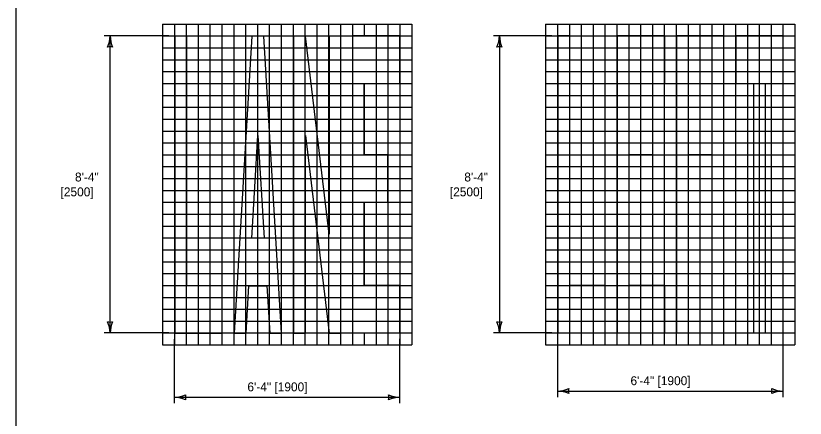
# Model space of a CAD drawing. Extents: x 49991.4 to 50021, y 49987.6 to 50011.4.
# Drawn here: x 50000.34 to 50005.66, y 50005.84 to 50008.55 of the extents above; entities that cross this region are included whole.
import ezdxf

# ---------------------------------------------------------------- set-up
doc = ezdxf.new("R2010")
doc.units = 0
for name, color, linetype in [('Level 1', 7, 'Continuous'), ('Level 2', 7, 'Continuous'), ('Level 3', 7, 'Continuous'), ('Level 9', 7, 'Continuous')]:
    doc.layers.add(name, color=color, linetype=linetype)

msp = doc.modelspace()

# ---------------------------------------------------------------- linework, layer by layer
at = {"layer": 'Level 1'}
for p, q in [((50001.4074, 50008.4148), (50001.4074, 50006.4142)), ((50001.4874, 50008.4148), (50001.4074, 50008.4148)), ((50001.4874, 50007.2145), (50001.4874, 50008.4148)), ((50001.9273, 50008.4148), (50001.8074, 50006.4142)), ((50002.0073, 50008.4148), (50001.9273, 50008.4148)), ((50002.1273, 50006.4142), (50002.0073, 50008.4148)), ((50002.2889, 50008.4148), (50002.2072, 50008.4148)), ((50002.2072, 50008.4148), (50002.2072, 50006.4142)), ((50002.4472, 50007.0825), (50002.2889, 50008.4148)), ((50002.5272, 50008.4148), (50002.4472, 50008.4148)), ((50002.4472, 50008.4148), (50002.4472, 50007.0825)), ((50002.5272, 50006.4142), (50002.5272, 50008.4148)), ((50002.924, 50008.4165), (50002.604, 50008.4165)), ((50002.604, 50008.4165), (50002.604, 50006.4159)), ((50002.924, 50008.0965), (50002.924, 50008.4165)), ((50003.9891, 50008.4169), (50003.9891, 50006.4163)), ((50004.0691, 50008.4169), (50003.9891, 50008.4169)), ((50003.9891, 50008.4169), (50003.9891, 50006.4163)), ((50004.0691, 50008.4169), (50003.9891, 50008.4169)), ((50004.0691, 50007.2164), (50004.0691, 50008.4169)), ((50004.0691, 50007.2164), (50004.0691, 50008.4169)), ((50004.7096, 50008.417), (50004.3897, 50008.417)), ((50004.3897, 50008.417), (50004.3897, 50006.4164)), ((50004.7096, 50008.417), (50004.3897, 50008.417)), ((50004.3897, 50008.417), (50004.3897, 50006.4164)), ((50004.7096, 50008.0969), (50004.7096, 50008.417)), ((50004.7096, 50008.0969), (50004.7096, 50008.417)), ((50005.1088, 50008.4169), (50004.7889, 50008.4169)), ((50004.7889, 50008.4169), (50004.7889, 50006.4163)), ((50005.1088, 50008.4169), (50004.7889, 50008.4169)), ((50004.7889, 50008.4169), (50004.7889, 50006.4163)), ((50005.1088, 50008.0967), (50005.1088, 50008.4169)), ((50005.1088, 50008.0967), (50005.1088, 50008.4169)), ((50005.5088, 50008.4169), (50005.1888, 50008.4169)), ((50005.1888, 50008.4169), (50005.1888, 50008.0967)), ((50005.5088, 50008.4169), (50005.1888, 50008.4169)), ((50005.1888, 50008.4169), (50005.1888, 50008.0967)), ((50005.5088, 50008.0967), (50005.5088, 50008.4169)), ((50005.5088, 50008.0967), (50005.5088, 50008.4169)), ((50002.6841, 50007.6162), (50002.6841, 50008.0965)), ((50002.6841, 50008.0965), (50002.924, 50008.0965)), ((50004.4696, 50007.6168), (50004.4696, 50008.0969)), ((50004.4696, 50008.0969), (50004.7096, 50008.0969)), ((50004.4696, 50007.6168), (50004.4696, 50008.0969)), ((50004.4696, 50008.0969), (50004.7096, 50008.0969)), ((50004.8689, 50007.6166), (50004.8689, 50008.0967)), ((50004.8689, 50008.0967), (50005.1088, 50008.0967)), ((50004.8689, 50007.6166), (50004.8689, 50008.0967)), ((50004.8689, 50008.0967), (50005.1088, 50008.0967)), ((50005.1888, 50008.0967), (50005.3088, 50008.0967)), ((50005.1888, 50008.0967), (50005.3088, 50008.0967)), ((50005.3088, 50008.0967), (50005.3088, 50006.4163)), ((50005.3088, 50008.0967), (50005.3088, 50006.4163)), ((50005.3888, 50006.4163), (50005.3888, 50008.0967)), ((50005.3888, 50008.0967), (50005.5088, 50008.0967)), ((50005.3888, 50006.4163), (50005.3888, 50008.0967)), ((50005.3888, 50008.0967), (50005.5088, 50008.0967)), ((50001.9265, 50007.0544), (50001.9681, 50007.7459)), ((50001.9681, 50007.7459), (50002.0089, 50007.0544)), ((50002.2872, 50006.4142), (50002.2872, 50007.7466)), ((50002.2872, 50007.7466), (50002.4472, 50006.4142)), ((50002.844, 50007.6162), (50002.6841, 50007.6162)), ((50002.844, 50007.2962), (50002.844, 50007.6162)), ((50004.6296, 50007.6168), (50004.4696, 50007.6168)), ((50004.6296, 50007.6168), (50004.4696, 50007.6168)), ((50004.6296, 50007.2967), (50004.6296, 50007.6168)), ((50004.6296, 50007.2967), (50004.6296, 50007.6168)), ((50005.0288, 50007.6166), (50004.8689, 50007.6166)), ((50005.0288, 50007.6166), (50004.8689, 50007.6166)), ((50005.0288, 50007.2966), (50005.0288, 50007.6166)), ((50005.0288, 50007.2966), (50005.0288, 50007.6166)), ((50002.6841, 50006.7359), (50002.6841, 50007.2962)), ((50002.6841, 50007.2962), (50002.844, 50007.2962)), ((50004.4696, 50006.7365), (50004.4696, 50007.2967)), ((50004.4696, 50007.2967), (50004.6296, 50007.2967)), ((50004.4696, 50006.7365), (50004.4696, 50007.2967)), ((50004.4696, 50007.2967), (50004.6296, 50007.2967)), ((50004.8689, 50006.4163), (50004.8689, 50007.2966)), ((50004.8689, 50007.2966), (50005.0288, 50007.2966)), ((50004.8689, 50006.4163), (50004.8689, 50007.2966)), ((50004.8689, 50007.2966), (50005.0288, 50007.2966)), ((50001.4874, 50006.7342), (50001.4874, 50007.2145)), ((50004.0691, 50006.7363), (50004.0691, 50007.2164)), ((50004.0691, 50006.7363), (50004.0691, 50007.2164)), ((50002.0089, 50007.0544), (50001.9265, 50007.0544)), ((50001.7274, 50006.7342), (50001.4874, 50006.7342)), ((50001.7274, 50006.4142), (50001.7274, 50006.7342)), ((50001.8873, 50006.4142), (50001.9065, 50006.7342)), ((50001.9065, 50006.7342), (50002.0281, 50006.7342)), ((50002.0281, 50006.7342), (50002.0473, 50006.4142)), ((50002.924, 50006.7359), (50002.6841, 50006.7359)), ((50002.924, 50006.4159), (50002.924, 50006.7359)), ((50004.3091, 50006.7363), (50004.0691, 50006.7363)), ((50004.3091, 50006.7363), (50004.0691, 50006.7363)), ((50004.3091, 50006.4163), (50004.3091, 50006.7363)), ((50004.3091, 50006.4163), (50004.3091, 50006.7363)), ((50004.7096, 50006.7365), (50004.4696, 50006.7365)), ((50004.7096, 50006.7365), (50004.4696, 50006.7365)), ((50004.7096, 50006.4164), (50004.7096, 50006.7365)), ((50004.7096, 50006.4164), (50004.7096, 50006.7365)), ((50001.4074, 50006.4142), (50001.7274, 50006.4142)), ((50001.8074, 50006.4142), (50001.8074, 50006.4142)), ((50001.8074, 50006.4142), (50001.8873, 50006.4142)), ((50002.0473, 50006.4142), (50002.1273, 50006.4142)), ((50002.2072, 50006.4142), (50002.2872, 50006.4142)), ((50002.4472, 50006.4142), (50002.5272, 50006.4142)), ((50002.604, 50006.4159), (50002.924, 50006.4159)), ((50003.9891, 50006.4163), (50004.3091, 50006.4163)), ((50003.9891, 50006.4163), (50004.3091, 50006.4163)), ((50004.3897, 50006.4164), (50004.7096, 50006.4164)), ((50004.3897, 50006.4164), (50004.7096, 50006.4164)), ((50004.7889, 50006.4163), (50004.8689, 50006.4163)), ((50004.7889, 50006.4163), (50004.8689, 50006.4163)), ((50005.3088, 50006.4163), (50005.3888, 50006.4163)), ((50005.3088, 50006.4163), (50005.3888, 50006.4163))]:
    msp.add_line(p, q, dxfattribs=at)
msp.add_lwpolyline([(50008.6146, 50011.2628), (50000.3356, 50011.2628), (50000.3356, 50000.0624), (50008.6146, 50000.0624)], close=True, dxfattribs=at)
at = {"layer": 'Level 3'}
for p, q in [((50001.3674, 50008.4165), (50000.9316, 50008.4165)), ((50000.9716, 50006.4159), (50000.9716, 50008.4165)), ((50003.9491, 50008.4165), (50003.5556, 50008.4165)), ((50003.5956, 50008.4165), (50003.5956, 50006.4159)), ((50005.5065, 50008.0567), (50005.5065, 50005.9843)), ((50001.3674, 50006.4159), (50000.9316, 50006.4159)), ((50003.9491, 50006.4159), (50003.5556, 50006.4159)), ((50001.4044, 50005.9428), (50001.4044, 50006.3742)), ((50002.9241, 50005.9428), (50002.9241, 50006.3759)), ((50003.9869, 50006.3763), (50003.9869, 50005.9843)), ((50001.4044, 50005.9828), (50002.9241, 50005.9828)), ((50003.9869, 50006.0243), (50005.5065, 50006.0243))]:
    msp.add_line(p, q, dxfattribs=at)
for centre, radius, start, end in [((50000.7495, 50008.4257), 0.2223, 337.456, 357.6395), ((50001.2043, 50008.428), 0.233, 182.8273, 202.0772), ((50003.3734, 50008.4257), 0.2223, 337.456, 357.6395), ((50003.8283, 50008.428), 0.233, 182.8273, 202.0772), ((50000.9716, 50008.2883), 0.0548, 72.1388, 107.8612), ((50003.5956, 50008.2883), 0.0548, 72.1388, 107.8612), ((50000.9716, 50006.5441), 0.0548, 252.1388, 287.8612), ((50000.7389, 50006.4044), 0.233, 2.8273, 22.0772), ((50001.1938, 50006.4067), 0.2223, 157.456, 177.6395), ((50003.5956, 50006.5441), 0.0548, 252.1388, 287.8612), ((50003.3629, 50006.4044), 0.233, 2.8273, 22.0772), ((50003.8177, 50006.4067), 0.2223, 157.456, 177.6395), ((50003.9777, 50006.2465), 0.2223, 272.3605, 292.544), ((50004.1151, 50006.0243), 0.0548, 162.1388, 197.8612), ((50005.5157, 50006.2465), 0.2223, 247.456, 267.6395), ((50005.3783, 50006.0243), 0.0548, 342.1388, 17.8612), ((50001.3953, 50006.2049), 0.2223, 272.3605, 292.544), ((50001.393, 50005.7501), 0.233, 67.9228, 87.1727), ((50001.5327, 50005.9828), 0.0548, 162.1388, 197.8612), ((50002.9333, 50006.2049), 0.2223, 247.456, 267.6395), ((50002.7959, 50005.9828), 0.0548, 342.1388, 17.8612), ((50002.9356, 50005.7501), 0.233, 92.8273, 112.0772), ((50003.9754, 50005.7916), 0.233, 67.9228, 87.1727), ((50005.518, 50005.7916), 0.233, 92.8273, 112.0772)]:
    msp.add_arc(centre, radius, start, end, dxfattribs=at)
at = {"layer": 'Level 9'}
for p, q in [((50001.3245, 50008.4966), (50001.3245, 50006.3358)), ((50001.3245, 50008.4966), (50003.0041, 50008.4966)), ((50001.4044, 50008.4966), (50001.4044, 50006.3358)), ((50001.4844, 50008.4966), (50001.4844, 50006.3358)), ((50001.5644, 50008.4966), (50001.5644, 50006.3358)), ((50001.6444, 50008.4966), (50001.6444, 50006.3358)), ((50001.7244, 50008.4966), (50001.7244, 50006.3358)), ((50001.8044, 50008.4966), (50001.8044, 50006.3358)), ((50001.8843, 50008.4966), (50001.8843, 50006.3358)), ((50001.9643, 50008.4966), (50001.9643, 50006.3358)), ((50002.0443, 50008.4966), (50002.0443, 50006.3358)), ((50002.1243, 50008.4966), (50002.1243, 50006.3358)), ((50002.2043, 50008.4966), (50002.2043, 50006.3358)), ((50002.2843, 50008.4966), (50002.2843, 50006.3358)), ((50002.3642, 50008.4966), (50002.3642, 50006.3358)), ((50002.4442, 50008.4966), (50002.4442, 50006.3358)), ((50002.5242, 50008.4966), (50002.5242, 50006.3358)), ((50002.6042, 50008.4966), (50002.6042, 50006.3358)), ((50002.6842, 50008.4966), (50002.6842, 50008.4165)), ((50002.7642, 50008.4966), (50002.7642, 50006.3358)), ((50002.8441, 50008.4966), (50002.8441, 50006.3358)), ((50002.9241, 50008.4966), (50002.9241, 50006.3358)), ((50003.0041, 50008.4966), (50003.0041, 50006.3358)), ((50003.9069, 50008.4966), (50005.5865, 50008.4966)), ((50003.9069, 50008.4966), (50003.9069, 50006.3358)), ((50003.9869, 50008.4966), (50003.9869, 50006.3358)), ((50004.0669, 50008.4966), (50004.0669, 50006.3358)), ((50004.1468, 50008.4966), (50004.1468, 50006.3358)), ((50004.2268, 50008.4966), (50004.2268, 50006.3358)), ((50004.3068, 50008.4966), (50004.3068, 50006.3358)), ((50004.3868, 50008.4966), (50004.3868, 50006.3358)), ((50004.4668, 50008.4966), (50004.4668, 50006.3358)), ((50004.5468, 50008.4966), (50004.5468, 50006.3358)), ((50004.6267, 50008.4966), (50004.6267, 50006.3358)), ((50004.7067, 50008.4966), (50004.7067, 50006.3358)), ((50004.7867, 50008.4966), (50004.7867, 50006.3358)), ((50004.8667, 50008.4966), (50004.8667, 50006.3358)), ((50004.9467, 50008.4966), (50004.9467, 50006.3358)), ((50005.0267, 50008.4966), (50005.0267, 50006.3358)), ((50005.1066, 50008.4966), (50005.1066, 50006.3358)), ((50005.1866, 50008.4966), (50005.1866, 50006.3358)), ((50005.2666, 50008.4966), (50005.2666, 50006.3358)), ((50005.3466, 50008.4966), (50005.3466, 50006.3358)), ((50005.4266, 50008.4966), (50005.4266, 50006.3358)), ((50005.5065, 50008.4966), (50005.5065, 50006.3358)), ((50005.5865, 50008.4966), (50005.5865, 50006.3358)), ((50001.3245, 50008.4165), (50003.0041, 50008.4165)), ((50003.9069, 50008.4165), (50005.5865, 50008.4165)), ((50001.3245, 50008.3365), (50003.0041, 50008.3365)), ((50003.9069, 50008.3365), (50005.5865, 50008.3365)), ((50001.3245, 50008.2565), (50003.0041, 50008.2565)), ((50003.9069, 50008.2565), (50005.5865, 50008.2565)), ((50001.3245, 50008.1765), (50003.0041, 50008.1765)), ((50001.4044, 50008.1765), (50002.9241, 50008.1765)), ((50003.9069, 50008.1765), (50005.5865, 50008.1765)), ((50003.9869, 50008.1765), (50005.5065, 50008.1765)), ((50004.706, 50008.1765), (50004.706, 50008.1765)), ((50001.3245, 50008.0964), (50003.0041, 50008.0964)), ((50001.4044, 50008.0964), (50002.9241, 50008.0964)), ((50002.6842, 50008.0965), (50002.6842, 50007.6163)), ((50003.9069, 50008.0964), (50005.5865, 50008.0964)), ((50003.9869, 50008.0964), (50005.5065, 50008.0964)), ((50001.3245, 50008.0164), (50003.0041, 50008.0164)), ((50003.9069, 50008.0164), (50005.5865, 50008.0164)), ((50001.3245, 50007.9364), (50003.0041, 50007.9364)), ((50003.9069, 50007.9364), (50005.5865, 50007.9364)), ((50001.3245, 50007.8563), (50003.0041, 50007.8563)), ((50003.9069, 50007.8563), (50005.5865, 50007.8563)), ((50001.3245, 50007.7763), (50003.0041, 50007.7763)), ((50003.9069, 50007.7763), (50005.5865, 50007.7763)), ((50001.3245, 50007.6963), (50003.0041, 50007.6963)), ((50003.9069, 50007.6963), (50005.5865, 50007.6963)), ((50001.3245, 50007.6163), (50003.0041, 50007.6163)), ((50003.9069, 50007.6163), (50005.5865, 50007.6163)), ((50001.3245, 50007.5362), (50003.0041, 50007.5362)), ((50003.9069, 50007.5362), (50005.5865, 50007.5362)), ((50001.3245, 50007.4562), (50003.0041, 50007.4562)), ((50003.9069, 50007.4562), (50005.5865, 50007.4562)), ((50001.3245, 50007.3762), (50003.0041, 50007.3762)), ((50003.9069, 50007.3762), (50005.5865, 50007.3762)), ((50001.3245, 50007.2962), (50003.0041, 50007.2962)), ((50002.6842, 50007.2961), (50002.6842, 50006.736)), ((50003.9069, 50007.2962), (50005.5865, 50007.2962)), ((50001.3245, 50007.2161), (50003.0041, 50007.2161)), ((50003.9069, 50007.2161), (50005.5865, 50007.2161)), ((50001.3245, 50007.1361), (50003.0041, 50007.1361)), ((50003.9069, 50007.1361), (50005.5865, 50007.1361)), ((50001.3245, 50007.0561), (50003.0041, 50007.0561)), ((50003.9069, 50007.0561), (50005.5865, 50007.0561)), ((50001.3245, 50006.976), (50003.0041, 50006.976)), ((50003.9069, 50006.976), (50005.5865, 50006.976)), ((50001.3245, 50006.896), (50003.0041, 50006.896)), ((50003.9069, 50006.896), (50005.5865, 50006.896)), ((50001.3245, 50006.816), (50003.0041, 50006.816)), ((50003.9069, 50006.816), (50005.5865, 50006.816)), ((50001.3245, 50006.736), (50003.0041, 50006.736)), ((50003.9069, 50006.736), (50005.5865, 50006.736)), ((50001.3245, 50006.6559), (50003.0041, 50006.6559)), ((50003.9069, 50006.6559), (50005.5865, 50006.6559)), ((50001.3245, 50006.5759), (50003.0041, 50006.5759)), ((50003.9069, 50006.5759), (50005.5865, 50006.5759)), ((50001.3245, 50006.4959), (50003.0041, 50006.4959)), ((50003.9069, 50006.4959), (50005.5865, 50006.4959)), ((50001.3245, 50006.4159), (50003.0041, 50006.4159)), ((50002.6842, 50006.4158), (50002.6842, 50006.3358)), ((50003.9069, 50006.4159), (50005.5865, 50006.4159)), ((50001.3245, 50006.3358), (50003.0041, 50006.3358)), ((50003.9069, 50006.3358), (50005.5865, 50006.3358))]:
    msp.add_line(p, q, dxfattribs=at)

# ---------------------------------------------------------------- texts
at = {"layer": 'Level 2'}
for s, p in [('8\'-4"', (50000.7347, 50007.4363)), ('8\'-4"', (50003.3586, 50007.4363)), ('[2500]', (50000.6373, 50007.3363)), ('[2500]', (50003.2613, 50007.3363)), ('6\'-4" [1900]', (50001.8968, 50006.0228)), ('6\'-4" [1900]', (50004.4788, 50006.0643))]:
    msp.add_text(s, height=0.06, dxfattribs=at).set_placement(p)

doc.saveas('drawing.dxf')
